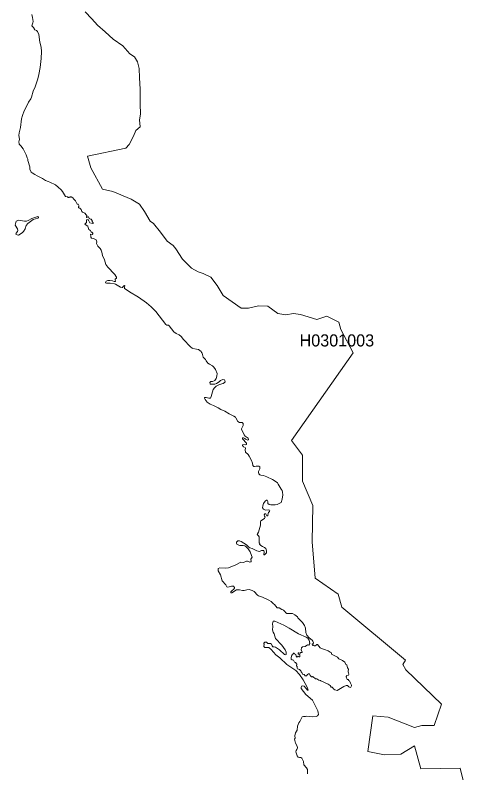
# Model space of a CAD drawing. Extents: x 369010 to 739155, y 6377141 to 6616555.
# Drawn here: x 377953 to 381708, y 6475665 to 6481931 of the extents above; entities that cross this region are included whole.
import ezdxf
from ezdxf.enums import TextEntityAlignment as Align

# ---------------------------------------------------------------- set-up
doc = ezdxf.new("R2010")
doc.units = 0
doc.header["$LTSCALE"] = 40
doc.layers.add('1', color=7, linetype='Continuous', lineweight=13)
doc.layers.add('2', color=7, linetype='Continuous')

msp = doc.modelspace()

# ---------------------------------------------------------------- linework, layer by layer
at = {"layer": '1'}
for points in [[(381708, 6475415.11), (381637.33, 6475703.42), (381310.79, 6475699.61), (381258.66, 6475888.12), (381145.62, 6475818.77), (381008.92, 6475813.31), (380872.21, 6475840.62), (380913.25, 6476135.88), (381039.04, 6476124.96), (381257.67, 6476040.22), (381317.75, 6476056.6), (381421.52, 6476056.6), (381481.76, 6476234.35), (381186.5, 6476515.88), (381162.01, 6476562.38), (381183.85, 6476597.97), (380656.89, 6477034.07), (380626.93, 6477143.3), (380435.61, 6477274.55), (380411.78, 6477574.77), (380417.24, 6477875.66), (380331.18, 6478078.4), (380331.18, 6478293.56), (380240.48, 6478414.54), (380751.39, 6479137.29), (380647.12, 6479331.1), (380630.41, 6479391.67), (380532.93, 6479442.15), (380448.85, 6479415.18), (380314.46, 6479455.56), (380257.2, 6479462.34), (380192.32, 6479452.75), (380127.94, 6479464.33), (380044.19, 6479524.91), (379967.56, 6479527.39), (379883.98, 6479507.2), (379823.58, 6479508.52), (379675.45, 6479613.28), (379625.96, 6479695.87), (379572.18, 6479764.06), (379508.79, 6479794.35), (379468.57, 6479809.41), (379413.29, 6479838.54), (379336.66, 6479913.01), (379281.38, 6479997.58), (379260.2, 6480026.05), (379210.38, 6480061.47), (379156.59, 6480135.95), (379097.34, 6480206.62), (379070.53, 6480226.81), (379022.21, 6480307.08), (378983.15, 6480366.33), (378911.81, 6480409.36), (378759.88, 6480472.42), (378674.98, 6480491.28), (378579.48, 6480668.04), (378552.51, 6480763.87), (378867.46, 6480829.57), (378895.76, 6480862.01), (378933.33, 6480928.88), (378950.87, 6480978.03), (378988.61, 6481005.84), (378981.82, 6481063.93), (378989.93, 6481113.08), (378987.28, 6481197.65), (378987.28, 6481318.31), (378983.15, 6481411.65), (378977.85, 6481489.93), (378964.28, 6481545.38), (378941.44, 6481584.6), (378901.06, 6481609.76), (378844.79, 6481676.13), (378764.02, 6481731.57), (378696.82, 6481792.14), (378634.93, 6481846.43), (378586.43, 6481899.56), (378531.32, 6481958.81)], [(378531.32, 6481958.81), (378586.43, 6481899.56), (378634.93, 6481846.43), (378696.82, 6481792.14), (378764.02, 6481731.57), (378844.79, 6481676.13), (378901.06, 6481609.76), (378941.44, 6481584.6), (378964.28, 6481545.38), (378977.85, 6481489.93), (378983.15, 6481411.65), (378987.28, 6481318.31), (378987.28, 6481197.65), (378989.93, 6481113.08), (378981.82, 6481063.93), (378988.61, 6481005.84), (378950.87, 6480978.03), (378933.33, 6480928.88), (378895.76, 6480862.01), (378867.46, 6480829.57), (378552.51, 6480763.87), (378579.48, 6480668.04), (378674.98, 6480491.28), (378759.88, 6480472.42), (378911.81, 6480409.36), (378983.15, 6480366.33), (379022.21, 6480307.08), (379070.53, 6480226.81), (379097.34, 6480206.62), (379156.59, 6480135.95), (379210.38, 6480061.47), (379260.2, 6480026.05), (379281.38, 6479997.58), (379336.66, 6479913.01), (379413.29, 6479838.54), (379468.57, 6479809.41), (379508.79, 6479794.35)], [(378090.25, 6481935.14), (378097.04, 6481911.31), (378101.18, 6481878.37), (378100.35, 6481867.95), (378091.58, 6481843.12), (378104.65, 6481827.73), (378111.93, 6481815.48), (378112.26, 6481812.17), (378115.57, 6481808.69), (378129.97, 6481804.06), (378137.92, 6481796.12), (378147.52, 6481769.8), (378157.12, 6481708.57), (378167.54, 6481665.04), (378170.85, 6481628.79), (378167.87, 6481570.87), (378159.76, 6481498.37), (378149.17, 6481440.45), (378140.57, 6481404.2), (378118.55, 6481338.99), (378102.67, 6481302.75), (378088.93, 6481251.94), (378081.65, 6481237.54), (378062.78, 6481210.56), (378050.7, 6481181.6), (378026.7, 6481138.07), (378012.8, 6481101.83), (378005.51, 6481072.86), (377996.91, 6481000.37), (377984.83, 6480956.85), (377983.83, 6480935.16), (377988.14, 6480906.2), (377986.15, 6480891.97), (377982.34, 6480885.18), (377987.14, 6480864), (378000.88, 6480849.6), (378018.42, 6480825.27), (378043.41, 6480775.78), (378051.36, 6480749.47), (378056.32, 6480738.88), (378056.66, 6480729.61), (378074.03, 6480676.98), (378074.7, 6480657.28), (378085.62, 6480631.13), (378093.23, 6480625.67), (378116.9, 6480613.43), (378133.61, 6480601.84), (378180.12, 6480580.49), (378203.13, 6480564.27)], [(378203.13, 6480564.27), (378226.13, 6480554.51), (378240.7, 6480550.2), (378287.86, 6480526.2), (378309.88, 6480508.99), (378334.87, 6480485.33), (378345.46, 6480472.08), (378370.12, 6480429.72), (378384.68, 6480429.05), (378392.13, 6480423.1), (378397.1, 6480423.43), (378399.41, 6480426.07), (378408.35, 6480426.07), (378411, 6480428.06), (378415.63, 6480428.06), (378429.7, 6480420.78), (378438.64, 6480408.2), (378452.87, 6480395.79), (378466.28, 6480368.31), (378468.26, 6480366.99), (378475.21, 6480367.32), (378482.83, 6480350.27), (378477.86, 6480347.29), (378475.88, 6480341.34), (378480.18, 6480337.03), (378488.29, 6480335.71), (378499.54, 6480324.62), (378505.5, 6480307.41), (378508.81, 6480302.77), (378528.84, 6480294), (378540.75, 6480280.76), (378544.73, 6480273.81), (378545.06, 6480266.86), (378542.74, 6480263.05), (378543.4, 6480258.75), (378547.04, 6480258.42), (378556.15, 6480263.38), (378559.79, 6480262.06), (378564.42, 6480248.16), (378575.01, 6480242.86), (378580.97, 6480242.86), (378586.6, 6480234.92), (378589.41, 6480233.76), (378589.74, 6480224.49), (378599.67, 6480214.56), (378599.01, 6480210.59), (378596.03, 6480208.27), (378571.04, 6480212.24), (378559.13, 6480235.91), (378556.15, 6480238.23), (378546.38, 6480240.88), (378542.08, 6480233.1), (378542.08, 6480216.88), (378529.5, 6480203.31), (378531.16, 6480198.84), (378555.15, 6480186.26), (378556.81, 6480175.67), (378563.1, 6480158.95), (378570.05, 6480152.33), (378575.68, 6480150.01), (378580.64, 6480137.1), (378588.42, 6480135.12), (378596.03, 6480126.68), (378595.7, 6480122.21), (378591.4, 6480117.91), (378576.83, 6480120.22), (378575.01, 6480115.75), (378579.65, 6480107.15), (378578.32, 6480094.4), (378585.27, 6480085.47), (378601.33, 6480083.81), (378622.35, 6480072.89), (378627.64, 6480056.5), (378626.65, 6480041.94), (378637.57, 6480020.26), (378655.28, 6480000.56), (378663.89, 6479986), (378669.19, 6479971.6), (378676.47, 6479942.47), (378691.2, 6479906.39), (378703.44, 6479870.15), (378720.16, 6479845.65), (378775.27, 6479788.06), (378777.92, 6479787.39), (378786.36, 6479772.33), (378792.65, 6479765.05), (378792.32, 6479755.78), (378780.57, 6479746.85), (378779.58, 6479739.73), (378782.22, 6479733.77), (378781.89, 6479729.47), (378772.29, 6479728.81), (378757.73, 6479733.44), (378736.71, 6479737.41), (378720.82, 6479736.09), (378706.42, 6479729.8), (378700.13, 6479721.19), (378700.13, 6479717.22), (378709.73, 6479714.9), (378738.7, 6479715.57)], [(379508.79, 6479794.35), (379572.18, 6479764.06), (379625.96, 6479695.87), (379675.45, 6479613.28), (379823.58, 6479508.52), (379883.98, 6479507.2), (379967.56, 6479527.39), (380044.19, 6479524.91), (380127.94, 6479464.33), (380192.32, 6479452.75), (380257.2, 6479462.34), (380314.46, 6479455.56), (380448.85, 6479415.18), (380532.93, 6479442.15), (380630.41, 6479391.67), (380647.12, 6479331.1), (380751.39, 6479137.29), (380240.48, 6478414.54), (380331.18, 6478293.56), (380331.18, 6478078.4), (380417.24, 6477875.66), (380411.78, 6477574.77), (380435.61, 6477274.55), (380626.93, 6477143.3), (380656.89, 6477034.07), (381183.85, 6476597.97), (381162.01, 6476562.38), (381186.5, 6476515.88), (381481.76, 6476234.35), (381421.52, 6476056.6), (381317.75, 6476056.6), (381257.67, 6476040.22), (381039.04, 6476124.96), (380913.25, 6476135.88), (380872.21, 6475840.62), (381008.92, 6475813.31), (381145.62, 6475818.77), (381258.66, 6475888.12), (381310.79, 6475699.61), (381637.33, 6475703.42), (381708, 6475415.11)], [(378738.7, 6479715.57), (378774.94, 6479708.45), (378784.21, 6479705.14), (378823.6, 6479681.64), (378837.5, 6479677.67), (378842.8, 6479678.66), (378844.79, 6479684.62), (378850.91, 6479692.56), (378856.54, 6479694.22), (378860.18, 6479691.57), (378858.85, 6479681.31), (378856.54, 6479678.66), (378858.85, 6479669.89), (378872.76, 6479661.61), (378898.41, 6479641.92), (378973.55, 6479597.4), (379039.42, 6479552.54), (379079.47, 6479518.62), (379116.38, 6479480.38), (379201.12, 6479373.47), (379209.06, 6479367.84), (379222.8, 6479367.18), (379228.75, 6479361.55), (379266.65, 6479312.56), (379286.02, 6479298), (379310.35, 6479286.08), (379325.57, 6479274.66), (379346.59, 6479249.01), (379402.7, 6479186.95), (379417.76, 6479176.19), (379424.38, 6479173.21), (379453.34, 6479169.24), (379469.56, 6479165.27), (379493.56, 6479148.22), (379496.21, 6479141.93), (379500.51, 6479136.96), (379509.95, 6479101.71), (379528.15, 6479083.01), (379533.45, 6479071.09), (379548.84, 6479054.21), (379562.08, 6479044.45), (379585.42, 6479031.54), (379597.99, 6479018.79), (379610.74, 6478999.26), (379624.64, 6478966.33), (379621.99, 6478946.63), (379615.37, 6478926.11), (379604.78, 6478910.72), (379599.65, 6478906.42), (379585.75, 6478902.11), (379572.01, 6478901.78), (379563.73, 6478894.17), (379566.38, 6478881.43), (379569.36, 6478878.78), (379591.04, 6478878.12), (379605.44, 6478880.43), (379620.01, 6478885.4), (379633.58, 6478892.85), (379645.33, 6478901.78), (379652.61, 6478909.73), (379671.31, 6478916.68), (379684.22, 6478916.02), (379688.52, 6478909.73), (379689.85, 6478899.8), (379686.54, 6478892.85), (379673.3, 6478885.73), (379644.34, 6478876.79), (379617.03, 6478863.88), (379601.3, 6478849.15), (379592.7, 6478835.25), (379575.82, 6478777.32), (379569.36, 6478763.75), (379556.12, 6478762.43), (379532.45, 6478769.38), (379523.52, 6478768.72), (379520.87, 6478767.06), (379520.21, 6478762.76), (379524.18, 6478752.99), (379542.55, 6478731.15), (379567.38, 6478714.43), (379595.68, 6478703.84), (379610.08, 6478694.24), (379634.24, 6478684.48), (379655.92, 6478670.24), (379687.53, 6478655.18), (379723.45, 6478633), (379763, 6478615.96), (379775.41, 6478607.68), (379780.38, 6478600.73), (379794.94, 6478571.77), (379808.35, 6478561.84), (379828.54, 6478563.16), (379832.51, 6478561.34), (379839.63, 6478553.4), (379840.29, 6478546.11), (379838.64, 6478538.83), (379825.23, 6478509.54), (379825.23, 6478505.24), (379838.97, 6478480.91), (379847.57, 6478459.23)], [(379847.57, 6478459.23), (379856.51, 6478450.62), (379873.56, 6478439.36), (379882.5, 6478431.42), (379883.82, 6478419.34), (379877.36, 6478415.7), (379860.48, 6478424.47), (379853.86, 6478430.76), (379843.27, 6478436.72), (379837.31, 6478436.72), (379834.66, 6478431.75), (379835.33, 6478427.61), (379867.27, 6478390.71), (379867.6, 6478381.44), (379863.13, 6478376.47), (379836.32, 6478379.12), (379834.17, 6478371.51), (379843.93, 6478361.41), (379855.19, 6478356.12), (379859.49, 6478349.83), (379856.18, 6478336.26), (379859.49, 6478317.55), (379881.5, 6478297.86), (379890.77, 6478285.28), (379909.47, 6478249.04), (379916.42, 6478227.35), (379919.73, 6478207.82), (379922.05, 6478203.19), (379927.02, 6478198.89), (379934.13, 6478198.39), (379948.7, 6478201.87), (379968.72, 6478201.87), (379977.33, 6478195.41), (379978.32, 6478187.14), (379976.67, 6478179.85), (379966.74, 6478158.17), (379966.07, 6478150.89), (379970.05, 6478137.32), (379978.98, 6478130.53), (379986.27, 6478127.56), (380007.95, 6478123.91), (380036.91, 6478114.31), (380083.75, 6478090.98), (380113.37, 6478072.11), (380125.29, 6478063.01), (380129.26, 6478052.75), (380153.26, 6478011.54), (380155.58, 6478010.54), (380162.69, 6477999.45), (380166, 6477984.89), (380167.66, 6477963.21), (380163.36, 6477928.29), (380154.25, 6477901.97), (380137.7, 6477891.71), (380122.64, 6477885.09), (380104.11, 6477881.78), (380069.18, 6477882.77), (380054.78, 6477885.42), (380044.52, 6477891.71), (380042.87, 6477909.09), (380039.23, 6477919.02), (380034.26, 6477920.34), (380021.85, 6477911.74), (380009.27, 6477892.04), (380002.32, 6477872.18), (380000.33, 6477857.78), (380006.95, 6477845.87), (380023.5, 6477837.76), (380047.5, 6477840.24), (380057.76, 6477837.1), (380060.41, 6477832.79), (380057.43, 6477826.5), (380048.83, 6477816.9), (380046.18, 6477810.28), (380044.85, 6477792.57), (380041.21, 6477789.6), (380036.58, 6477791.58), (380029.13, 6477801.51), (380027.81, 6477805.98), (380023.5, 6477808.3), (380018.54, 6477807.3), (380012.91, 6477799.86), (380015.23, 6477788.6), (380021.52, 6477779), (380017.88, 6477769.24), (379985.6, 6477748.72), (379983.29, 6477739.78), (379984.61, 6477733.32), (379983.29, 6477713.46), (379968.06, 6477654.21), (379957.97, 6477640.81), (379956.97, 6477637.5), (379968.06, 6477625.91), (379971.37, 6477616.64), (379973.69, 6477566.99), (379976.67, 6477562.36), (379976.34, 6477557.39), (379985.6, 6477545.81), (379998.68, 6477536.71), (380015.23, 6477529.09)], [(380015.23, 6477529.09), (380026.81, 6477520.82), (380031.95, 6477501.45), (380032.61, 6477483.25), (380015.56, 6477468.52), (380011.26, 6477468.52), (380013.24, 6477492.85), (380011.59, 6477501.78), (380008.61, 6477504.76), (379992.89, 6477504.43), (379974.18, 6477496.32), (379952.01, 6477501.12), (379915.76, 6477519.49), (379895.74, 6477525.78), (379887.13, 6477531.74), (379866.94, 6477550.11), (379823.58, 6477578.08), (379809.01, 6477583.71), (379796.27, 6477585.03), (379785.34, 6477572.95), (379784.35, 6477564.01), (379788.32, 6477556.4), (379803.72, 6477547.79), (379811, 6477546.14), (379839.96, 6477545.48), (379854.53, 6477542.33), (379863.13, 6477537.7), (379881.83, 6477517.84), (379898.05, 6477491.52), (379910.13, 6477463.22), (379913.78, 6477448.66), (379903.85, 6477431.94), (379905.5, 6477412.74), (379903.85, 6477409.27), (379895.4, 6477407.61), (379874.88, 6477415.72), (379867.6, 6477415.39), (379842.61, 6477404.3), (379821.59, 6477406.62), (379814.97, 6477405.3), (379780.05, 6477384.44), (379718.81, 6477360.78), (379689.85, 6477357.8), (379645.66, 6477361.44), (379633.58, 6477355.81), (379631.92, 6477335.45), (379650.96, 6477303.18), (379666.84, 6477253.36), (379696.14, 6477219.43), (379703.42, 6477202.39), (379713.52, 6477200.4), (379743.14, 6477209.01), (379760.35, 6477208.68), (379767.64, 6477198.08), (379767.64, 6477191.13), (379760.68, 6477181.04), (379752.41, 6477175.74), (379737.51, 6477161.84), (379738.84, 6477155.22), (379747.44, 6477154.56), (379783.69, 6477177.4), (379809.67, 6477179.05), (379835.66, 6477172.76), (379849.23, 6477172.76), (379869.25, 6477178.39), (379888.78, 6477180.04), (379915.1, 6477173.42), (379930.33, 6477163.83), (379958.96, 6477133.54), (379967.07, 6477128.57), (379999.67, 6477116.82), (380052.14, 6477092.99), (380071.17, 6477080.91), (380091.69, 6477062.04), (380098.15, 6477058.4), (380122.64, 6477030.43), (380138.36, 6477029.44), (380159.22, 6477015.37), (380168.65, 6477013.71), (380173.29, 6477011.07), (380186.2, 6476997.49), (380189.84, 6476990.21), (380201.92, 6476982.43), (380227.9, 6476984.09), (380247.76, 6476981.77), (380268.78, 6476972.17), (380288.48, 6476954.46), (380293.61, 6476946.35), (380331.67, 6476907.63), (380348.89, 6476884.45), (380354.84, 6476862.61), (380358.82, 6476826.2), (380366.43, 6476804.35), (380384.97, 6476781.84), (380411.45, 6476763.31), (380417.74, 6476753.38), (380422.7, 6476739.47), (380420.38, 6476732.85), (380414.09, 6476732.19), (380411.78, 6476729.21)], [(380308.5, 6476623.62), (380307.84, 6476639.84), (380294.93, 6476650.43), (380295.59, 6476657.71), (380299.9, 6476658.71), (380307.84, 6476654.4), (380311.48, 6476654.74), (380317.44, 6476660.03), (380326.05, 6476659.7), (380327.04, 6476664), (380320.42, 6476682.54), (380323.4, 6476698.1), (380332.34, 6476708.69), (380352.2, 6476711.01), (380371.39, 6476722.59), (380384.63, 6476722.26), (380391.92, 6476733.85), (380385.96, 6476763.64), (380374.37, 6476777.87), (380362.13, 6476787.8), (380296.59, 6476814.28), (380221.12, 6476862.94), (380177.59, 6476887.76), (380101.46, 6476920.2), (380087.89, 6476919.21), (380081.93, 6476897.69), (380085.9, 6476874.52), (380083.91, 6476846.72), (380088.22, 6476828.85), (380097.49, 6476814.28), (380108.41, 6476775.88), (380161.04, 6476719.94), (380186.36, 6476683.86), (380195.3, 6476662.68), (380196.62, 6476647.45), (380194.64, 6476644.47), (380189.34, 6476642.49), (380181.89, 6476644.47), (380140.52, 6476683.53), (380108.74, 6476704.39), (380097.49, 6476707.37), (380084.91, 6476706.7), (380078.95, 6476715.64), (380074.31, 6476728.55), (380067.03, 6476735.17), (380045.19, 6476736.16), (380032.94, 6476744.77), (380018.04, 6476746.76), (380011.75, 6476738.48), (380011.42, 6476732.52), (380014.07, 6476728.55), (380011.42, 6476709.68), (380019.7, 6476701.08), (380051.14, 6476702.73), (380072.99, 6476685.19), (380109.07, 6476640.5), (380142.83, 6476616.34), (380201.26, 6476562.05), (380276.39, 6476511.74), (380304.86, 6476479.47), (380335.98, 6476433.79), (380369.08, 6476374.21), (380379.17, 6476348.55), (380373.55, 6476348.22), (380344.91, 6476381.16), (380332.67, 6476386.12), (380322.07, 6476381.49), (380318.76, 6476370.9), (380320.42, 6476362.95), (380358.48, 6476312.97), (380412.44, 6476264.97), (380426.01, 6476243.13), (380456.79, 6476177.59), (380461.1, 6476163.02), (380462.42, 6476147.8), (380455.8, 6476135.88), (380444.55, 6476130.25), (380412.44, 6476128.6), (380364.11, 6476135.22), (380354.84, 6476130.58), (380340.28, 6476130.58), (380328.36, 6476127.6), (380310.16, 6476090.86), (380300.56, 6476077.62), (380290.3, 6476051.14), (380285.99, 6476018.04), (380271.76, 6475994.87), (380268.45, 6475971.7), (380271.1, 6475951.84), (380265.8, 6475942.9), (380274.41, 6475912.12), (380285.99, 6475885.8), (380288.64, 6475872.56), (380284.01, 6475859.32), (380277.72, 6475849.39), (380276.73, 6475839.46), (380287.98, 6475806.36), (380295.92, 6475794.45), (380305.19, 6475792.13), (380317.11, 6475792.79)], [(380411.78, 6476729.21), (380413.43, 6476720.61), (380415.42, 6476718.95), (380419.39, 6476721.93), (380424.02, 6476721.93), (380428.33, 6476716.96), (380434.62, 6476715.97), (380444.55, 6476720.61), (380450.84, 6476727.23), (380455.8, 6476727.23), (380477.98, 6476700.08), (380487.58, 6476692.8), (380513.73, 6476686.18), (380542.19, 6476674.6), (380560.73, 6476662.35), (380572.32, 6476659.04), (380570.66, 6476651.42), (380571.98, 6476646.79), (380621.64, 6476622.63), (380631.57, 6476609.39), (380662.02, 6476595.15), (380680.56, 6476580.26), (380689.82, 6476561.06), (380696.77, 6476558.74), (380702.4, 6476534.25), (380712.66, 6476522.99), (380709.68, 6476502.47), (380710.68, 6476489.73), (380713.99, 6476485.09), (380714.32, 6476478.47), (380710.68, 6476474.17), (380694.13, 6476471.52), (380692.8, 6476464.9), (380694.79, 6476461.26), (380692.8, 6476457.95), (380699.42, 6476437.1), (380711.01, 6476438.09), (380712.66, 6476428.82), (380720.94, 6476425.84), (380727.56, 6476405.98), (380736.16, 6476391.09), (380736.5, 6476386.12), (380730.87, 6476374.21), (380726.57, 6476372.22), (380714.98, 6476375.86), (380703.06, 6476387.78), (380693.13, 6476387.45), (380673.94, 6476379.83), (380632.89, 6476353.35), (380616.67, 6476346.73), (380597.8, 6476351.37), (380590.52, 6476356.33), (380576.95, 6476374.21), (380569.34, 6476372.88), (380559.08, 6476386.45), (380544.84, 6476397.71), (380483.27, 6476426.84), (380480.63, 6476430.15), (380467.06, 6476432.79), (380450.84, 6476441.73), (380437.6, 6476441.4), (380419.39, 6476460.6), (380412.77, 6476462.25), (380410.12, 6476459.27), (380406.81, 6476459.27), (380395.23, 6476470.2), (380389.27, 6476482.78), (380381.99, 6476483.77), (380373.71, 6476477.81), (380364.77, 6476467.55), (380353.19, 6476467.22), (380345.24, 6476477.81), (380332.34, 6476482.45), (380326.71, 6476496.02), (380319.76, 6476501.48), (380318.1, 6476510.08), (380305.19, 6476519.68), (380290.63, 6476525.64), (380287.32, 6476531.6), (380287.32, 6476543.52), (380280.37, 6476551.46), (380283.35, 6476563.38), (380274.41, 6476576.95), (380264.81, 6476581.91), (380256.2, 6476598.46), (380245.61, 6476598.79), (380236.67, 6476604.42), (380237.34, 6476616.34), (380243.96, 6476640.17), (380251.9, 6476639.84), (380254.22, 6476654.07), (380259.51, 6476655.4), (380264.48, 6476648.45), (380276.39, 6476645.14), (380279.37, 6476628.92), (380283.68, 6476622.96), (380287.32, 6476623.29), (380295.59, 6476628.92), (380302.21, 6476623.29), (380308.5, 6476623.62)], [(380317.11, 6475792.79), (380326.71, 6475785.84), (380338.96, 6475758.7), (380341.27, 6475732.22), (380363.45, 6475707.06), (380373.71, 6475692.16), (380371.39, 6475656.08)]]:
    msp.add_lwpolyline(points, dxfattribs=at)
msp.add_lwpolyline([(377982.51, 6480235.25), (377961.82, 6480227.47), (377952.55, 6480195.2), (377972.25, 6480162.59), (377975.56, 6480150.68), (377971.92, 6480140.41), (377960.5, 6480128.99), (377959.5, 6480120.72), (377970.59, 6480112.78), (377981.19, 6480110.79), (378011.47, 6480130.65), (378022.06, 6480141.41), (378035.14, 6480162.59), (378045.07, 6480192.22), (378056.66, 6480208.93), (378101.67, 6480240.54), (378140.57, 6480253.12), (378145.86, 6480258.75), (378145.53, 6480263.38), (378139.9, 6480266.2), (378091.91, 6480250.47), (378061.62, 6480232.1), (378046.39, 6480226.48), (378030.51, 6480225.81)], close=True, dxfattribs=at)

# ---------------------------------------------------------------- texts
at = {"layer": '2'}
msp.add_text('H0301003', height=100, dxfattribs=at).set_placement((380615.36, 6479191.14), align=Align.CENTER)

doc.saveas('drawing.dxf')
